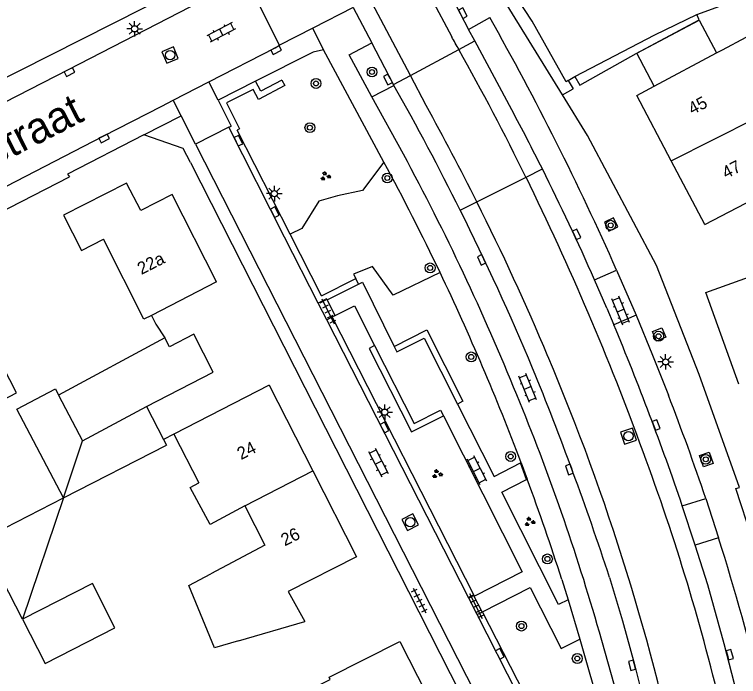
# Model space of a CAD drawing. Extents: x 136000 to 138005, y 398500 to 400500.
# Drawn here: x 137669 to 137727.4, y 398528.4 to 398581.8 of the extents above; entities that cross this region are included whole.
import ezdxf

# ---------------------------------------------------------------- set-up
doc = ezdxf.new("R2010")
doc.units = 0
for name, color, linetype in [('gg-afsc-erfafscheiding', 7, 'Continuous'), ('gg-afsc-muur', 7, 'Continuous'), ('gg-anno-huisnummerreeks BGT', 7, 'Continuous'), ('gg-anno-openbare ruimte label', 7, 'Continuous'), ('gg-bbg-bijgebouw', 7, 'Continuous'), ('gg-bbg-gedigitaliseerde bebouwing', 7, 'Continuous'), ('gg-bbg-gedigitaliseerde bijgebouw', 7, 'Continuous'), ('gg-bbg-hoofdgebouw', 7, 'Continuous'), ('gg-bbg-luifel en loopbrug', 7, 'Continuous'), ('gg-bbg-tussenscheiding', 7, 'Continuous'), ('gg-knt-verharding', 7, 'Continuous'), ('gg-knt-verharding nz', 7, 'Continuous'), ('gt-grn-groengrens', 7, 'Continuous'), ('gt-grn-weggrens', 7, 'Continuous'), ('gt-symb-boom', 7, 'Continuous'), ('gt-symb-groenvak', 7, 'Continuous'), ('gt-symb-klinker verharding', 7, 'Continuous'), ('gt-symb-kolk', 7, 'Continuous'), ('gt-symb-lichtmast', 7, 'Continuous'), ('gt-symb-rioolschacht', 7, 'Continuous'), ('gt-symb-tegel verharding', 7, 'Continuous')]:
    doc.layers.add(name, color=color, linetype=linetype)

# ---------------------------------------------------------------- blocks, each defined once
blk = doc.blocks.new('gt0-KOLK')
at = {"layer": 'gt-symb-kolk'}
blk.add_lwpolyline([(0, 0), (0.375, 0), (0.375, 0.4), (-0.375, 0.4), (-0.375, 0), (0, 0)], dxfattribs=at)
blk = doc.blocks.new('gt0-KL1')
at = {"layer": 'gt-symb-klinker verharding'}
for p, q in [((-1.15, 0.3), (1.15, 0.3)), ((-1, -0.3), (-1, 0.3)), ((-0.5, 0.3), (-0.5, 0.45)), ((0, -0.3), (0, 0.3)), ((0.5, 0.3), (0.5, 0.45)), ((1, -0.3), (1, 0.3)), ((-1.15, -0.3), (1.15, -0.3)), ((-0.5, -0.45), (-0.5, -0.3)), ((0.5, -0.45), (0.5, -0.3))]:
    blk.add_line(p, q, dxfattribs=at)
blk = doc.blocks.new('gt0-LMAST')
at = {"layer": 'gt-symb-lichtmast'}
for p, q in [((-0.005, 0.246), (-0.005, 0.621)), ((-0.182, 0.173), (-0.447, 0.438)), ((0.172, 0.173), (0.437, 0.438)), ((-0.255, -0.004), (-0.63, -0.004)), ((-0.182, -0.181), (-0.447, -0.446)), ((-0.005, -0.254), (-0.005, -0.629)), ((0.437, -0.446), (0.172, -0.181)), ((0.245, -0.004), (0.62, -0.004))]:
    blk.add_line(p, q, dxfattribs=at)
blk.add_circle((-0.005, -0.004), 0.25, dxfattribs=at)
blk = doc.blocks.new('gt0-GRVAK')
at = {"layer": 'gt-symb-groenvak'}
for p, q in [((-0.11, 0.189), (-0.228, 0.24)), ((-0.182, 0.153), (0.088, 0.153)), ((-0.091, 0.211), (-0.156, 0.322)), ((-0.047, 0.214), (-0.047, 0.393)), ((-0.004, 0.211), (0.061, 0.322)), ((0.015, 0.189), (0.133, 0.24)), ((0.262, -0.052), (0.197, 0.059)), ((0.305, -0.049), (0.305, 0.13)), ((0.349, -0.052), (0.414, 0.059)), ((-0.245, -0.228), (-0.363, -0.177)), ((-0.318, -0.264), (-0.047, -0.264)), ((-0.226, -0.206), (-0.291, -0.095)), ((-0.183, -0.203), (-0.183, -0.024)), ((-0.139, -0.206), (-0.074, -0.095)), ((-0.12, -0.228), (-0.002, -0.177)), ((0.243, -0.074), (0.125, -0.023)), ((0.17, -0.11), (0.441, -0.11)), ((0.368, -0.074), (0.486, -0.023))]:
    blk.add_line(p, q, dxfattribs=at)
blk = doc.blocks.new('gt0-BOOM')
at = {"layer": 'gt-symb-boom'}
for radius in [0.4, 0.2]:
    blk.add_circle((0, 0), radius, dxfattribs=at)
blk = doc.blocks.new('gt0-TEG1')
at = {"layer": 'gt-symb-tegel verharding'}
for p, q in [((-1.125, 0), (1.125, 0)), ((-0.9, -0.25), (-0.9, 0.25)), ((-0.45, -0.25), (-0.45, 0.25)), ((0, -0.25), (0, 0.25)), ((0.45, -0.25), (0.45, 0.25)), ((0.9, -0.25), (0.9, 0.25))]:
    blk.add_line(p, q, dxfattribs=at)
blk = doc.blocks.new('gt0-RS')
at = {"layer": 'gt-symb-rioolschacht'}
blk.add_lwpolyline([(-0.5, -0.5), (0.5, -0.5), (0.5, 0.5), (-0.5, 0.5)], close=True, dxfattribs=at)
blk.add_circle((0, 0), 0.375, dxfattribs=at)

msp = doc.modelspace()

# ---------------------------------------------------------------- linework, layer by layer
at = {"layer": 'gg-afsc-erfafscheiding'}
msp.add_line((137724, 398581.745), (137727.35, 398583), dxfattribs=at)
msp.add_lwpolyline([(137680.041, 398557.508), (137680.394, 398556.82), (137681.132, 398555.698)], dxfattribs=at)
at = {"layer": 'gg-afsc-muur'}
msp.add_line((137681.853, 398547.948), (137681.023, 398547.521), dxfattribs=at)
at = {"layer": 'gg-bbg-bijgebouw'}
for p, q in [((137679.661, 398550.185), (137681.023, 398547.521)), ((137681.023, 398547.521), (137681.252, 398547.073))]:
    msp.add_line(p, q, dxfattribs=at)
msp.add_lwpolyline([(137679.661, 398550.185), (137685.027, 398552.95), (137683.453, 398555.996), (137681.5, 398554.994), (137681.132, 398555.698)], dxfattribs=at)
at = {"layer": 'gg-bbg-gedigitaliseerde bebouwing'}
for p, q in [((137679.443, 398557.2), (137676.19, 398563.661)), ((137681.853, 398547.948), (137683.873, 398544.028)), ((137687.053, 398531.298), (137692.42, 398532.85))]:
    msp.add_line(p, q, dxfattribs=at)
for points in [[(137726.086, 398578.917), (137729.882, 398580.937), (137731.016, 398578.806)], [(137672.96, 398565.58), (137674.409, 398562.749), (137676.19, 398563.661)], [(137666.261, 398549.779), (137669.162, 398551.272), (137665.29, 398558.78)], [(137687.569, 398542.171), (137684.77, 398540.67), (137683.171, 398543.651), (137683.873, 398544.028)], [(137687.569, 398542.171), (137689.183, 398538.997), (137684.823, 398536.71)], [(137687.053, 398531.298), (137685.127, 398530.741), (137683.058, 398535.763), (137684.823, 398536.71)]]:
    msp.add_lwpolyline(points, dxfattribs=at)
at = {"layer": 'gg-bbg-gedigitaliseerde bijgebouw'}
for p, q in [((137681.132, 398555.698), (137672.564, 398551.101)), ((137672.952, 398542.834), (137681.252, 398547.073))]:
    msp.add_line(p, q, dxfattribs=at)
for points in [[(137672.952, 398542.834), (137669.209, 398549.97), (137672.305, 398551.594), (137672.564, 398551.101)], [(137669.658, 398533.041), (137671.476, 398529.475), (137677.111, 398532.347), (137675.293, 398535.913), (137669.658, 398533.041)]]:
    msp.add_lwpolyline(points, dxfattribs=at)
at = {"layer": 'gg-bbg-hoofdgebouw'}
for p, q in [((137720.572, 398575.983), (137725.604, 398578.661)), ((137725.604, 398578.661), (137726.086, 398578.917)), ((137724.65, 398564.85), (137721.946, 398569.962)), ((137685.3, 398560.22), (137680.041, 398557.508)), ((137680.041, 398557.508), (137679.443, 398557.2)), ((137689.55, 398551.91), (137681.853, 398547.948)), ((137689.55, 398551.91), (137693.065, 398544.995)), ((137700.06, 398531.24), (137703.316, 398524.891))]:
    msp.add_line(p, q, dxfattribs=at)
for points in [[(137721.946, 398569.962), (137719.16, 398575.231), (137720.572, 398575.983)], [(137724.65, 398564.85), (137731.221, 398568.256), (137731.926, 398566.957), (137735.912, 398569.033)], [(137685.3, 398560.22), (137681.73, 398567.26), (137679.19, 398565.96), (137678.05, 398568.17), (137672.96, 398565.58)], [(137727.386, 398551.978), (137724.74, 398559.36), (137731.998, 398561.962), (137732.082, 398561.726), (137736.111, 398563.17), (137738.591, 398556.252), (137734.562, 398554.807), (137734.651, 398554.559)], [(137693.065, 398544.995), (137696.58, 398538.08), (137691.06, 398535.27), (137692.42, 398532.85)], [(137690.629, 398526.265), (137694.453, 398528.188), (137694.363, 398528.368), (137700.06, 398531.24)]]:
    msp.add_lwpolyline(points, dxfattribs=at)
at = {"layer": 'gg-bbg-luifel en loopbrug'}
msp.add_line((137672.952, 398542.834), (137669.658, 398533.041), dxfattribs=at)
for points in [[(137720.572, 398575.983), (137719.163, 398578.631), (137724.195, 398581.309), (137725.604, 398578.661)], [(137669.658, 398533.041), (137666.363, 398539.441), (137672.952, 398542.834)]]:
    msp.add_lwpolyline(points, dxfattribs=at)
at = {"layer": 'gg-bbg-tussenscheiding'}
for p, q in [((137721.946, 398569.962), (137738.163, 398578.153)), ((137672.564, 398551.101), (137674.494, 398547.421)), ((137674.494, 398547.421), (137679.661, 398550.185)), ((137672.952, 398542.834), (137674.494, 398547.421)), ((137687.569, 398542.171), (137693.065, 398544.995))]:
    msp.add_line(p, q, dxfattribs=at)
at = {"layer": 'gg-knt-verharding'}
for p, q in [((137698.284, 398591.271), (137704.249, 398579.961)), ((137700.916, 398576.828), (137694.859, 398588.338)), ((137690.382, 398579.276), (137687.643, 398584.687)), ((137703.516, 398584.527), (137705.607, 398580.557)), ((137696.304, 398582.321), (137697.813, 398579.461)), ((137705.607, 398580.557), (137707.312, 398581.511)), ((137706.111, 398579.62), (137705.607, 398580.557)), ((137699.566, 398576.102), (137697.813, 398579.461)), ((137704.83, 398578.931), (137706.111, 398579.62)), ((137709.089, 398574.079), (137706.111, 398579.62)), ((137698.79, 398569.87), (137693.929, 398578.906)), ((137700.916, 398576.828), (137704.83, 398578.931)), ((137699.566, 398576.102), (137700.916, 398576.828)), ((137702.187, 398574.412), (137700.916, 398576.828)), ((137681.788, 398574.847), (137684.67, 398576.325)), ((137688.448, 398576.373), (137685.422, 398574.847)), ((137713.63, 398576.45), (137714.173, 398576.763)), ((137697.812, 398575.112), (137699.597, 398576.043)), ((137699.597, 398576.043), (137699.566, 398576.102)), ((137700.363, 398570.491), (137697.812, 398575.112)), ((137680.876, 398574.38), (137681.788, 398574.847)), ((137685.422, 398574.847), (137686.474, 398572.767)), ((137686.277, 398572.667), (137686.474, 398572.767)), ((137686.277, 398572.667), (137683.59, 398571.305)), ((137690.783, 398563.826), (137686.277, 398572.667)), ((137683.59, 398571.305), (137717.047, 398505.756)), ((137683.19, 398569.83), (137716.44, 398504.46)), ((137710.239, 398568.648), (137711.559, 398569.309)), ((137582.78, 398522.25), (137673.433, 398568.681)), ((137706.275, 398566.662), (137710.239, 398568.648)), ((137704.937, 398565.991), (137706.275, 398566.662)), ((137693.498, 398558.501), (137690.783, 398563.826)), ((137717.538, 398561.169), (137719.108, 398557.538)), ((137694.203, 398558.766), (137696.744, 398560.033)), ((137716.753, 398558.096), (137715.762, 398560.381)), ((137694.864, 398557.506), (137694.203, 398558.766)), ((137694.18, 398557.164), (137693.498, 398558.501)), ((137716.753, 398558.096), (137717.313, 398556.77)), ((137694.18, 398557.164), (137694.627, 398557.388)), ((137705.62, 398534.738), (137694.18, 398557.164)), ((137694.627, 398557.388), (137694.864, 398557.506)), ((137710.29, 398544.29), (137709.8, 398545.63)), ((137709.843, 398545.652), (137710.341, 398544.316)), ((137724.726, 398542.77), (137725.759, 398539.602)), ((137723.881, 398539.019), (137722.838, 398542.169)), ((137713.124, 398536.249), (137713.631, 398534.6)), ((137706.099, 398534.899), (137706.063, 398534.881)), ((137706.71, 398533.63), (137706.063, 398534.881)), ((137706.294, 398533.417), (137705.62, 398534.738)), ((137713.631, 398534.6), (137714.574, 398531.451)), ((137706.628, 398533.588), (137706.71, 398533.63)), ((137706.71, 398533.63), (137706.739, 398533.645)), ((137706.294, 398533.417), (137706.362, 398533.452)), ((137715.18, 398516.037), (137706.294, 398533.417)), ((137706.362, 398533.452), (137706.628, 398533.588)), ((137717.655, 398526.716), (137716.154, 398531.997)), ((137718.974, 398529.388), (137719.743, 398526.423))]:
    msp.add_line(p, q, dxfattribs=at)
for points in [[(137686.898, 398586.151), (137681.9, 398583.55), (137661.88, 398573.42), (137660.16, 398572.71), (137578.87, 398530.95)], [(137713.186, 398575.271), (137706.47, 398586.18), (137706.295, 398586.672)], [(137687.643, 398584.687), (137673.348, 398577.295), (137633.08, 398556.67)], [(137714.173, 398576.763), (137720.626, 398580.102), (137724, 398581.745)], [(137684.67, 398576.325), (137690.009, 398579.062), (137690.382, 398579.276)], [(137697.812, 398575.112), (137695.975, 398578.496), (137697.813, 398579.461)], [(137693.929, 398578.906), (137693.079, 398578.709), (137688.448, 398576.373)], [(137732.09, 398540.66), (137728.46, 398539.56), (137727.16, 398543.58), (137727.46, 398543.66), (137724.2, 398552.76), (137720.75, 398561.531), (137715.2, 398572), (137713.186, 398575.271)], [(137635.882, 398551.296), (137642.323, 398554.603), (137653.431, 398560.273), (137666.781, 398567.122), (137676.145, 398571.954), (137680.876, 398574.38)], [(137679.439, 398572.062), (137673.277, 398568.896), (137673.433, 398568.681)], [(137683.19, 398569.83), (137682.614, 398570.963), (137679.439, 398572.062)], [(137716.565, 398565.036), (137716.904, 398564.297), (137717.64, 398564.647), (137717.302, 398565.386), (137716.565, 398565.036)], [(137696.744, 398560.033), (137697.06, 398560.19), (137699.609, 398555.019)], [(137694.203, 398558.766), (137694.164, 398558.841), (137693.498, 398558.501)], [(137694.864, 398557.506), (137696.42, 398558.28), (137698.039, 398555.087)], [(137719.108, 398557.538), (137720.439, 398554.319), (137721.72, 398551.084)], [(137720.441, 398556.208), (137721.192, 398556.509), (137721.498, 398555.753), (137720.747, 398555.453), (137720.441, 398556.208)], [(137699.609, 398555.019), (137699.83, 398554.57), (137702.02, 398555.69), (137704.707, 398550.379)], [(137698.039, 398555.087), (137701.22, 398548.81), (137703.36, 398549.871), (137703.586, 398549.425)], [(137704.707, 398550.379), (137707.66, 398544.54), (137709.8, 398545.63)], [(137703.586, 398549.425), (137709.94, 398536.87), (137706.099, 398534.899)], [(137724.231, 398546.229), (137725.005, 398546.488), (137725.312, 398545.579), (137724.538, 398545.32), (137724.231, 398546.229)], [(137713.631, 398534.6), (137712.87, 398534.22), (137708.3, 398543.27), (137710.29, 398544.29)], [(137727.444, 398526.285), (137726.224, 398531.064), (137724.891, 398535.812), (137723.881, 398539.019)], [(137716.972, 398536.416), (137718.008, 398532.914), (137718.974, 398529.388)], [(137706.739, 398533.645), (137710.57, 398535.6), (137713.06, 398530.68), (137714.574, 398531.451)], [(137706.063, 398534.881), (137706.029, 398534.947), (137705.62, 398534.738)], [(137714.574, 398531.451), (137716.314, 398525.348), (137717.945, 398519.215), (137718.321, 398517.251)]]:
    msp.add_lwpolyline(points, dxfattribs=at)
for centre, radius, start, end in [((137505.756, 398467.447), 231.594, 23.87138, 29.50632), ((137426.256, 398422.472), 319.504, 29.32034, 29.53241), ((137511.864, 398470.864), 221.165, 26.23981, 29.25017), ((137508.422, 398468.039), 219.574, 26.49369, 29.46414), ((137519.777, 398473.24), 208.589, 26.60744, 29.01441), ((137535.458, 398481.145), 196.937, 26.5946, 28.15742), ((137527.937, 398477.381), 195.959, 22.10112, 28.36916), ((137497.641, 398462.047), 228.225, 25.68688, 28.19284), ((137532.589, 398479.603), 200.194, 23.79723, 26.62171), ((137512.64, 398471.28), 220.286, 19.9702, 26.23189), ((137519.488, 398473.068), 208.924, 22.85667, 26.61416), ((137508.493, 398468.135), 219.467, 22.8243, 26.47957), ((137524.247, 398475.583), 198.383, 20.68315, 25.49449), ((137509.077, 398469.628), 225.734, 18.74495, 22.70821), ((137542.175, 398482.273), 184.443, 11.48672, 22.95935), ((137474.398, 398456.794), 255.307, 18.1719, 22.20217), ((137547.138, 398483.85), 175.74, 15.90046, 22.5022), ((137543.732, 398482.03), 190.914, 18.55118, 21.20463), ((137552.742, 398484.401), 178.119, 13.2269, 20.40918), ((137525.271, 398475.956), 197.292, 17.79449, 20.27292), ((137543.417, 398481.866), 191.264, 13.58902, 17.56955)]:
    msp.add_arc(centre, radius, start, end, dxfattribs=at)
at = {"layer": 'gg-knt-verharding nz'}
for p, q in [((137715.762, 398560.381), (137717.538, 398561.169)), ((137719.108, 398557.538), (137717.313, 398556.77)), ((137722.838, 398542.169), (137724.726, 398542.77)), ((137725.759, 398539.602), (137723.881, 398539.019))]:
    msp.add_line(p, q, dxfattribs=at)
at = {"layer": 'gt-grn-groengrens'}
for p, q in [((137713.63, 398576.45), (137714.029, 398575.757)), ((137714.173, 398576.763), (137714.572, 398576.069)), ((137688.237, 398575.707), (137686.094, 398574.626)), ((137713.186, 398575.271), (137714.029, 398575.757)), ((137686.094, 398574.626), (137687.146, 398572.546)), ((137687.146, 398572.546), (137686.95, 398572.447)), ((137691.229, 398564.051), (137686.95, 398572.447)), ((137693.754, 398559.101), (137691.229, 398564.051)), ((137693.754, 398559.101), (137696.521, 398560.48)), ((137696.744, 398560.033), (137696.521, 398560.48)), ((137706.099, 398534.899), (137694.627, 398557.388)), ((137709.843, 398545.652), (137709.8, 398545.63)), ((137710.341, 398544.316), (137710.29, 398544.29)), ((137715.649, 398516.218), (137706.739, 398533.645))]:
    msp.add_line(p, q, dxfattribs=at)
for points in [[(137713.63, 398576.45), (137713.471, 398576.331), (137710.728, 398581.204), (137706.868, 398587.109), (137706.295, 398586.672)], [(137714.572, 398576.069), (137719.117, 398578.611), (137724.191, 398581.313), (137724, 398581.745)], [(137690.56, 398576.475), (137690.796, 398576.033), (137688.668, 398574.9), (137688.237, 398575.707)], [(137690.56, 398576.475), (137688.874, 398575.576), (137688.448, 398576.373)], [(137698.79, 398569.87), (137697.071, 398567.585), (137695.053, 398567.143), (137693.529, 398566.72), (137692.16, 398564.522), (137691.229, 398564.051)], [(137703.312, 398560.972), (137699.532, 398559.143), (137697.869, 398561.442), (137696.346, 398560.832), (137696.521, 398560.48)], [(137699.609, 398555.019), (137702.239, 398556.364), (137705.153, 398550.605), (137704.707, 398550.379)], [(137698.039, 398555.087), (137697.593, 398554.861), (137700.998, 398548.142), (137703.586, 398549.425)]]:
    msp.add_lwpolyline(points, dxfattribs=at)
at = {"layer": 'gt-grn-weggrens'}
for p, q in [((137696.304, 398582.321), (137693.044, 398580.645)), ((137693.044, 398580.645), (137690.382, 398579.276)), ((137693.929, 398578.906), (137693.044, 398580.645)), ((137685.422, 398574.847), (137684.67, 398576.325)), ((137682.431, 398573.584), (137681.788, 398574.847)), ((137679.439, 398572.062), (137682.431, 398573.584)), ((137683.59, 398571.305), (137682.431, 398573.584))]:
    msp.add_line(p, q, dxfattribs=at)

# ---------------------------------------------------------------- block references
at = {"layer": 'gt-symb-boom'}
for p in [(137697.828, 398577.119), (137693.314, 398576.201), (137692.821, 398572.639), (137699.058, 398568.585), (137717.066, 398564.774), (137702.51, 398561.34), (137720.921, 398555.84), (137705.824, 398554.171), (137709.002, 398546.153), (137724.724, 398545.922), (137711.965, 398537.9), (137714.373, 398529.881)]:
    msp.add_blockref('gt0-BOOM', p, dxfattribs=at)
at = {"layer": 'gt-symb-boom', "rotation": -70.6044716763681}
msp.add_blockref('gt0-BOOM', (137709.871, 398532.494), dxfattribs=at)
at = {"layer": 'gt-symb-groenvak'}
for p in [(137694.061, 398568.722), (137703.067, 398544.742), (137710.527, 398540.886)]:
    msp.add_blockref('gt0-GRVAK', p, dxfattribs=at)
at = {"layer": 'gt-symb-klinker verharding'}
for p, rotation in [((137685.671, 398580.316), -152.23078731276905), ((137717.877, 398557.899), 112.46117570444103), ((137710.373, 398551.67), 111.71629047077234), ((137698.346, 398545.665), -62.66592414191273), ((137706.27, 398545.068), -62.9993452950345)]:
    msp.add_blockref('gt0-KL1', p, dxfattribs=dict(at, rotation=rotation))
at = {"layer": 'gt-symb-kolk'}
for p, rotation in [((137704.974, 398581.759), -62.23078731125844), ((137690.009, 398579.062), -152.8574991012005), ((137673.348, 398577.295), -152.64097939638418), ((137699.29, 398576.62), 118.02531606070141), ((137676.145, 398571.954), -152.70227846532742), ((137686.879, 398571.499), -63.048796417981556), ((137689.808, 398565.739), -62.983810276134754), ((137714.141, 398563.961), -65.10079947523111), ((137706.838, 398562.078), 115.33527699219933), ((137698.653, 398548.389), -62.95857765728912), ((137720.542, 398548.612), -69.51770311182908), ((137713.92, 398545.174), 110.24750150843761), ((137707.954, 398530.165), -62.9116318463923), ((137726.469, 398530.141), -75.28268885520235), ((137718.974, 398529.388), 104.7173111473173)]:
    msp.add_blockref('gt0-KOLK', p, dxfattribs=dict(at, rotation=rotation))
at = {"layer": 'gt-symb-lichtmast'}
for p in [(137678.697, 398580.604), (137689.96, 398567.332), (137721.499, 398553.776), (137698.86, 398549.727)]:
    msp.add_blockref('gt0-LMAST', p, dxfattribs=at)
at = {"layer": 'gt-symb-rioolschacht'}
for p, rotation in [((137681.555, 398578.481), -156.9306877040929), ((137718.5, 398547.79), 19.03307980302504), ((137700.908, 398540.858), 116.99814488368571)]:
    msp.add_blockref('gt0-RS', p, dxfattribs=dict(at, rotation=rotation))
at = {"layer": 'gt-symb-tegel verharding'}
for p, rotation in [((137694.279, 398557.842), -64.02428534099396), ((137701.651, 398534.554), -62.99934529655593), ((137706.204, 398534.101), -63.1274610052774)]:
    msp.add_blockref('gt0-TEG1', p, dxfattribs=dict(at, rotation=rotation))

# ---------------------------------------------------------------- texts
at = {"layer": 'gg-anno-huisnummerreeks BGT'}
for s, rotation, p in [('45', 27.8, (137723.645, 398573.646)), ('47', 27.9, (137726.371, 398568.489)), ('22a', 26.9, (137679.231, 398560.768)), ('24', 26.9, (137687.267, 398545.859)), ('26', 26.9, (137690.799, 398538.911))]:
    msp.add_text(s, height=1, rotation=rotation, dxfattribs=at).set_placement(p)
at = {"layer": 'gg-anno-openbare ruimte label'}
msp.add_text('Vrijheidsstraat', height=2.5, rotation=27.1, dxfattribs=at).set_placement((137655.891, 398563.605))

doc.saveas('drawing.dxf')
